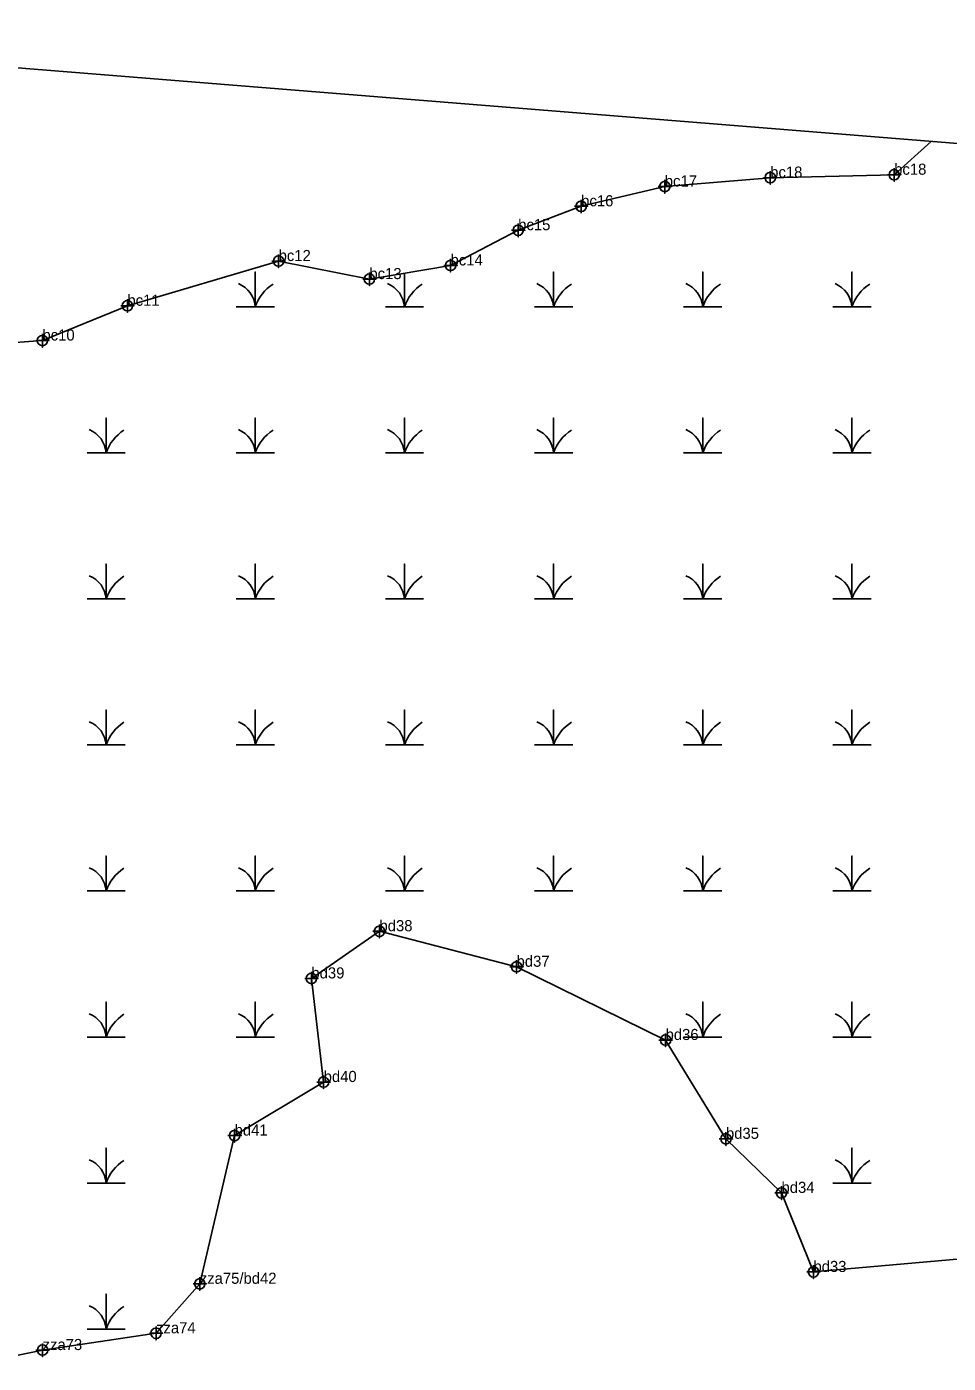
# Model space of a CAD drawing. Extents: x 2071991 to 2268989, y 436479 to 469629.
# Drawn here: x 2214880 to 2215295, y 439449 to 440051 of the extents above; entities that cross this region are included whole.
import ezdxf

# ---------------------------------------------------------------- set-up
doc = ezdxf.new("R2010")
doc.units = 0
for name, color, linetype in [('approx_PSA', 7, 'Continuous'), ('Exist Environmental Wetland Boundary', 7, 'Continuous'), ('Exist Environmental Wetland Boundary Cogo Comment', 7, 'Continuous'), ('Exist Environmental Wetland Boundary Cogo Point CELL', 7, 'Continuous'), ('Exist Hydro Swamp or Marsh', 7, 'Continuous')]:
    doc.layers.add(name, color=color, linetype=linetype)

msp = doc.modelspace()

# ---------------------------------------------------------------- linework, layer by layer
at = {"layer": 'approx_PSA'}
msp.add_line((2214861.68, 440033.95), (2215666.21, 439969.08), dxfattribs=at)
at = {"layer": 'Exist Environmental Wetland Boundary'}
for points in [[(2214643, 440051.24), (2214640.79, 440044.09), (2214670.86, 440006.51), (2214705.05, 439986.15), (2214750.6, 439980.47), (2214768.48, 439956.79), (2214803.77, 439915.77), (2214846.21, 439906.91), (2214887.26, 439909.88), (2214925.55, 439925.54), (2214993.67, 439945.68), (2215034.57, 439937.55), (2215071.14, 439943.7), (2215101.61, 439959.58), (2215129.98, 439970.34), (2215167.67, 439979.26), (2215215.16, 439983.25), (2215271.02, 439984.57), (2215287.64, 439999.61)], [(2214858.58, 439449.17), (2214887.32, 439455.11), (2214938.43, 439462.67), (2214958.15, 439484.96), (2214973.84, 439551.74), (2215013.96, 439575.86), (2215008.43, 439622.52), (2215039.12, 439643.79), (2215100.88, 439627.77), (2215168.02, 439594.78), (2215195.22, 439550.26), (2215220.25, 439525.91), (2215234.65, 439490.29), (2215306.13, 439496.6)]]:
    msp.add_lwpolyline(points, dxfattribs=at)
at = {"layer": 'Exist Environmental Wetland Boundary Cogo Point CELL'}
for points in [[(2215167.67, 439982.26), (2215167.67, 439976.26), (2215167.67, 439979.26), (2215170.67, 439979.26), (2215164.67, 439979.26)], [(2215215.16, 439986.25), (2215215.16, 439980.25), (2215215.16, 439983.25), (2215218.16, 439983.25), (2215212.16, 439983.25)], [(2215271.02, 439987.57), (2215271.02, 439981.57), (2215271.02, 439984.57), (2215274.02, 439984.57), (2215268.02, 439984.57)], [(2215129.98, 439973.34), (2215129.98, 439967.34), (2215129.98, 439970.34), (2215132.98, 439970.34), (2215126.98, 439970.34)], [(2215101.61, 439962.58), (2215101.61, 439956.58), (2215101.61, 439959.58), (2215104.61, 439959.58), (2215098.61, 439959.58)], [(2214993.67, 439948.68), (2214993.67, 439942.68), (2214993.67, 439945.68), (2214996.67, 439945.68), (2214990.67, 439945.68)], [(2215071.14, 439946.7), (2215071.14, 439940.7), (2215071.14, 439943.7), (2215074.14, 439943.7), (2215068.14, 439943.7)], [(2215034.57, 439940.55), (2215034.57, 439934.55), (2215034.57, 439937.55), (2215037.57, 439937.55), (2215031.57, 439937.55)], [(2214925.55, 439928.54), (2214925.55, 439922.54), (2214925.55, 439925.54), (2214928.55, 439925.54), (2214922.55, 439925.54)], [(2214887.26, 439912.88), (2214887.26, 439906.88), (2214887.26, 439909.88), (2214890.26, 439909.88), (2214884.26, 439909.88)], [(2215039.12, 439646.79), (2215039.12, 439640.79), (2215039.12, 439643.79), (2215042.12, 439643.79), (2215036.12, 439643.79)], [(2215100.88, 439630.77), (2215100.88, 439624.77), (2215100.88, 439627.77), (2215103.88, 439627.77), (2215097.88, 439627.77)], [(2215008.43, 439625.52), (2215008.43, 439619.52), (2215008.43, 439622.52), (2215011.43, 439622.52), (2215005.43, 439622.52)], [(2215168.02, 439597.78), (2215168.02, 439591.78), (2215168.02, 439594.78), (2215171.02, 439594.78), (2215165.02, 439594.78)], [(2215013.96, 439578.86), (2215013.96, 439572.86), (2215013.96, 439575.86), (2215016.96, 439575.86), (2215010.96, 439575.86)], [(2214973.84, 439554.74), (2214973.84, 439548.74), (2214973.84, 439551.74), (2214976.84, 439551.74), (2214970.84, 439551.74)], [(2215195.22, 439553.26), (2215195.22, 439547.26), (2215195.22, 439550.26), (2215198.22, 439550.26), (2215192.22, 439550.26)], [(2215220.25, 439528.91), (2215220.25, 439522.91), (2215220.25, 439525.91), (2215223.25, 439525.91), (2215217.25, 439525.91)], [(2215234.65, 439493.29), (2215234.65, 439487.29), (2215234.65, 439490.29), (2215237.65, 439490.29), (2215231.65, 439490.29)], [(2214958.15, 439487.96), (2214958.15, 439481.96), (2214958.15, 439484.96), (2214961.15, 439484.96), (2214955.15, 439484.96)], [(2214938.43, 439465.67), (2214938.43, 439459.67), (2214938.43, 439462.67), (2214941.43, 439462.67), (2214935.43, 439462.67)], [(2214887.32, 439458.11), (2214887.32, 439452.11), (2214887.32, 439455.11), (2214890.32, 439455.11), (2214884.32, 439455.11)]]:
    msp.add_lwpolyline(points, dxfattribs=at)
for centre in [(2215215.16, 439983.25), (2215271.02, 439984.57), (2215167.67, 439979.26), (2215129.98, 439970.34), (2215101.61, 439959.58), (2214993.67, 439945.68), (2215071.14, 439943.7), (2215034.57, 439937.55), (2214925.55, 439925.54), (2214887.26, 439909.88), (2215039.12, 439643.79), (2215100.88, 439627.77), (2215008.43, 439622.52), (2215168.02, 439594.78), (2215013.96, 439575.86), (2214973.84, 439551.74), (2215195.22, 439550.26), (2215220.25, 439525.91), (2215234.65, 439490.29), (2214958.15, 439484.96), (2214938.43, 439462.67), (2214887.32, 439455.11)]:
    msp.add_circle(centre, 2.34, dxfattribs=at)
at = {"layer": 'Exist Hydro Swamp or Marsh'}
msp.add_line((2214924.32, 439925.04), (2214924.55, 439925.04), dxfattribs=at)
for points in [[(2214974.55, 439925.04), (2214983.15, 439925.04), (2214983.15, 439940.82), (2214983.15, 439925.04), (2214991.75, 439925.04)], [(2215041.75, 439925.04), (2215050.36, 439925.04), (2215050.36, 439940.2)], [(2215050.36, 439940.2), (2215050.36, 439925.04), (2215058.96, 439925.04)], [(2215108.96, 439925.04), (2215117.56, 439925.04), (2215117.56, 439940.82), (2215117.56, 439925.04), (2215126.16, 439925.04)], [(2215176.16, 439925.04), (2215184.76, 439925.04), (2215184.76, 439940.82), (2215184.76, 439925.04), (2215193.36, 439925.04)], [(2215243.36, 439925.04), (2215251.97, 439925.04), (2215251.97, 439940.82), (2215251.97, 439925.04), (2215260.57, 439925.04)], [(2214907.35, 439859.26), (2214915.95, 439859.26), (2214915.95, 439875.04), (2214915.95, 439859.26), (2214924.55, 439859.26)], [(2214974.55, 439859.26), (2214983.15, 439859.26), (2214983.15, 439875.04), (2214983.15, 439859.26), (2214991.75, 439859.26)], [(2215041.75, 439859.26), (2215050.36, 439859.26), (2215050.36, 439875.04), (2215050.36, 439859.26), (2215058.96, 439859.26)], [(2215108.96, 439859.26), (2215117.56, 439859.26), (2215117.56, 439875.04), (2215117.56, 439859.26), (2215126.16, 439859.26)], [(2215176.16, 439859.26), (2215184.76, 439859.26), (2215184.76, 439875.04), (2215184.76, 439859.26), (2215193.36, 439859.26)], [(2215243.36, 439859.26), (2215251.97, 439859.26), (2215251.97, 439875.04), (2215251.97, 439859.26), (2215260.57, 439859.26)], [(2214907.35, 439793.48), (2214915.95, 439793.48), (2214915.95, 439809.26), (2214915.95, 439793.48), (2214924.55, 439793.48)], [(2214974.55, 439793.48), (2214983.15, 439793.48), (2214983.15, 439809.26), (2214983.15, 439793.48), (2214991.75, 439793.48)], [(2215041.75, 439793.48), (2215050.36, 439793.48), (2215050.36, 439809.26), (2215050.36, 439793.48), (2215058.96, 439793.48)], [(2215108.96, 439793.48), (2215117.56, 439793.48), (2215117.56, 439809.26), (2215117.56, 439793.48), (2215126.16, 439793.48)], [(2215176.16, 439793.48), (2215184.76, 439793.48), (2215184.76, 439809.26), (2215184.76, 439793.48), (2215193.36, 439793.48)], [(2215243.36, 439793.48), (2215251.97, 439793.48), (2215251.97, 439809.26), (2215251.97, 439793.48), (2215260.57, 439793.48)], [(2214907.35, 439727.7), (2214915.95, 439727.7), (2214915.95, 439743.48), (2214915.95, 439727.7), (2214924.55, 439727.7)], [(2214974.55, 439727.7), (2214983.15, 439727.7), (2214983.15, 439743.48), (2214983.15, 439727.7), (2214991.75, 439727.7)], [(2215041.75, 439727.7), (2215050.36, 439727.7), (2215050.36, 439743.48), (2215050.36, 439727.7), (2215058.96, 439727.7)], [(2215108.96, 439727.7), (2215117.56, 439727.7), (2215117.56, 439743.48), (2215117.56, 439727.7), (2215126.16, 439727.7)], [(2215176.16, 439727.7), (2215184.76, 439727.7), (2215184.76, 439743.48), (2215184.76, 439727.7), (2215193.36, 439727.7)], [(2215243.36, 439727.7), (2215251.97, 439727.7), (2215251.97, 439743.48), (2215251.97, 439727.7), (2215260.57, 439727.7)], [(2214907.35, 439661.92), (2214915.95, 439661.92), (2214915.95, 439677.7), (2214915.95, 439661.92), (2214924.55, 439661.92)], [(2214974.55, 439661.92), (2214983.15, 439661.92), (2214983.15, 439677.7), (2214983.15, 439661.92), (2214991.75, 439661.92)], [(2215041.75, 439661.92), (2215050.36, 439661.92), (2215050.36, 439677.7), (2215050.36, 439661.92), (2215058.96, 439661.92)], [(2215108.96, 439661.92), (2215117.56, 439661.92), (2215117.56, 439677.7), (2215117.56, 439661.92), (2215126.16, 439661.92)], [(2215176.16, 439661.92), (2215184.76, 439661.92), (2215184.76, 439677.7), (2215184.76, 439661.92), (2215193.36, 439661.92)], [(2215243.36, 439661.92), (2215251.97, 439661.92), (2215251.97, 439677.7), (2215251.97, 439661.92), (2215260.57, 439661.92)], [(2214907.35, 439596.14), (2214915.95, 439596.14), (2214915.95, 439611.92), (2214915.95, 439596.14), (2214924.55, 439596.14)], [(2214974.55, 439596.14), (2214983.15, 439596.14), (2214983.15, 439611.92), (2214983.15, 439596.14), (2214991.75, 439596.14)], [(2215176.16, 439596.14), (2215184.76, 439596.14), (2215184.76, 439611.92), (2215184.76, 439596.14), (2215193.36, 439596.14)], [(2215243.36, 439596.14), (2215251.97, 439596.14), (2215251.97, 439611.92), (2215251.97, 439596.14), (2215260.57, 439596.14)], [(2214907.35, 439530.36), (2214915.95, 439530.36), (2214915.95, 439546.14), (2214915.95, 439530.36), (2214924.55, 439530.36)], [(2215243.36, 439530.36), (2215251.97, 439530.36), (2215251.97, 439546.14), (2215251.97, 439530.36), (2215260.57, 439530.36)], [(2214907.35, 439464.57), (2214915.95, 439464.57), (2214915.95, 439480.36), (2214915.95, 439464.57), (2214924.55, 439464.57)]]:
    msp.add_lwpolyline(points, dxfattribs=at)
for centre, radius, start, end in [((2214970.89, 439924.15), 12.3, 4.14034, 67.53497), ((2215001.39, 439918.98), 19.22, 122.12745, 161.62219), ((2215038.09, 439924.15), 12.3, 4.14034, 67.53497), ((2215068.6, 439918.98), 19.22, 122.12745, 161.62219), ((2215105.29, 439924.15), 12.3, 4.14034, 67.53497), ((2215135.8, 439918.98), 19.22, 122.12745, 161.62219), ((2215172.5, 439924.15), 12.3, 4.14034, 67.53497), ((2215203, 439918.98), 19.22, 122.12745, 161.62219), ((2215239.7, 439924.15), 12.3, 4.14034, 67.53497), ((2215270.21, 439918.98), 19.22, 122.12745, 161.62219), ((2214903.68, 439858.37), 12.3, 4.14034, 67.53497), ((2214934.19, 439853.2), 19.22, 122.12745, 161.62219), ((2214970.89, 439858.37), 12.3, 4.14034, 67.53497), ((2215001.39, 439853.2), 19.22, 122.12745, 161.62219), ((2215038.09, 439858.37), 12.3, 4.14034, 67.53497), ((2215068.6, 439853.2), 19.22, 122.12745, 161.62219), ((2215105.29, 439858.37), 12.3, 4.14034, 67.53497), ((2215135.8, 439853.2), 19.22, 122.12745, 161.62219), ((2215172.5, 439858.37), 12.3, 4.14034, 67.53497), ((2215203, 439853.2), 19.22, 122.12745, 161.62219), ((2215239.7, 439858.37), 12.3, 4.14034, 67.53497), ((2215270.21, 439853.2), 19.22, 122.12745, 161.62219), ((2214903.68, 439792.59), 12.3, 4.14034, 67.53497), ((2214934.19, 439787.42), 19.22, 122.12745, 161.62219), ((2214970.89, 439792.59), 12.3, 4.14034, 67.53497), ((2215001.39, 439787.42), 19.22, 122.12745, 161.62219), ((2215038.09, 439792.59), 12.3, 4.14034, 67.53497), ((2215068.6, 439787.42), 19.22, 122.12745, 161.62219), ((2215105.29, 439792.59), 12.3, 4.14034, 67.53497), ((2215135.8, 439787.42), 19.22, 122.12745, 161.62219), ((2215172.5, 439792.59), 12.3, 4.14034, 67.53497), ((2215203, 439787.42), 19.22, 122.12745, 161.62219), ((2215239.7, 439792.59), 12.3, 4.14034, 67.53497), ((2215270.21, 439787.42), 19.22, 122.12745, 161.62219), ((2214903.68, 439726.81), 12.3, 4.14034, 67.53497), ((2214934.19, 439721.64), 19.22, 122.12745, 161.62219), ((2214970.89, 439726.81), 12.3, 4.14034, 67.53497), ((2215001.39, 439721.64), 19.22, 122.12745, 161.62219), ((2215038.09, 439726.81), 12.3, 4.14034, 67.53497), ((2215068.6, 439721.64), 19.22, 122.12745, 161.62219), ((2215105.29, 439726.81), 12.3, 4.14034, 67.53497), ((2215135.8, 439721.64), 19.22, 122.12745, 161.62219), ((2215172.5, 439726.81), 12.3, 4.14034, 67.53497), ((2215203, 439721.64), 19.22, 122.12745, 161.62219), ((2215239.7, 439726.81), 12.3, 4.14034, 67.53497), ((2215270.21, 439721.64), 19.22, 122.12745, 161.62219), ((2214903.68, 439661.03), 12.3, 4.14034, 67.53497), ((2214934.19, 439655.86), 19.22, 122.12745, 161.62219), ((2214970.89, 439661.03), 12.3, 4.14034, 67.53497), ((2215001.39, 439655.86), 19.22, 122.12745, 161.62219), ((2215038.09, 439661.03), 12.3, 4.14034, 67.53497), ((2215068.6, 439655.86), 19.22, 122.12745, 161.62219), ((2215105.29, 439661.03), 12.3, 4.14034, 67.53497), ((2215135.8, 439655.86), 19.22, 122.12745, 161.62219), ((2215172.5, 439661.03), 12.3, 4.14034, 67.53497), ((2215203, 439655.86), 19.22, 122.12745, 161.62219), ((2215239.7, 439661.03), 12.3, 4.14034, 67.53497), ((2215270.21, 439655.86), 19.22, 122.12745, 161.62219), ((2214903.68, 439595.25), 12.3, 4.14034, 67.53497), ((2214934.19, 439590.08), 19.22, 122.12745, 161.62219), ((2214970.89, 439595.25), 12.3, 4.14034, 67.53497), ((2215001.39, 439590.08), 19.22, 122.12745, 161.62219), ((2215172.5, 439595.25), 12.3, 4.14034, 67.53497), ((2215203, 439590.08), 19.22, 122.12745, 161.62219), ((2215239.7, 439595.25), 12.3, 4.14034, 67.53497), ((2215270.21, 439590.08), 19.22, 122.12745, 161.62219), ((2214903.68, 439529.47), 12.3, 4.14034, 67.53497), ((2214934.19, 439524.29), 19.22, 122.12745, 161.62219), ((2215239.7, 439529.47), 12.3, 4.14034, 67.53497), ((2215270.21, 439524.29), 19.22, 122.12745, 161.62219), ((2214903.68, 439463.69), 12.3, 4.14034, 67.53497), ((2214934.19, 439458.51), 19.22, 122.12745, 161.62219)]:
    msp.add_arc(centre, radius, start, end, dxfattribs=at)

# ---------------------------------------------------------------- texts
at = {"layer": 'Exist Environmental Wetland Boundary Cogo Comment'}
for s, p in [('bc18', (2215215.16, 439983.25)), ('bc18', (2215271.02, 439984.57)), ('bc17', (2215167.67, 439979.26)), ('bc16', (2215129.98, 439970.34)), ('bc15', (2215101.61, 439959.58)), ('bc12', (2214993.67, 439945.68)), ('bc14', (2215071.14, 439943.7)), ('bc13', (2215034.57, 439937.55)), ('bc11', (2214925.55, 439925.54)), ('bc10', (2214887.26, 439909.88)), ('bd38', (2215039.12, 439643.79)), ('bd37', (2215100.88, 439627.77)), ('bd39', (2215008.43, 439622.52)), ('bd36', (2215168.02, 439594.78)), ('bd40', (2215013.96, 439575.86)), ('bd41', (2214973.84, 439551.74)), ('bd35', (2215195.22, 439550.26)), ('bd34', (2215220.25, 439525.91)), ('bd33', (2215234.65, 439490.29)), ('zza75/bd42', (2214958.15, 439484.96)), ('zza74', (2214938.43, 439462.67)), ('zza73', (2214887.32, 439455.11))]:
    msp.add_text(s, height=5, dxfattribs=at).set_placement(p)

doc.saveas('drawing.dxf')
